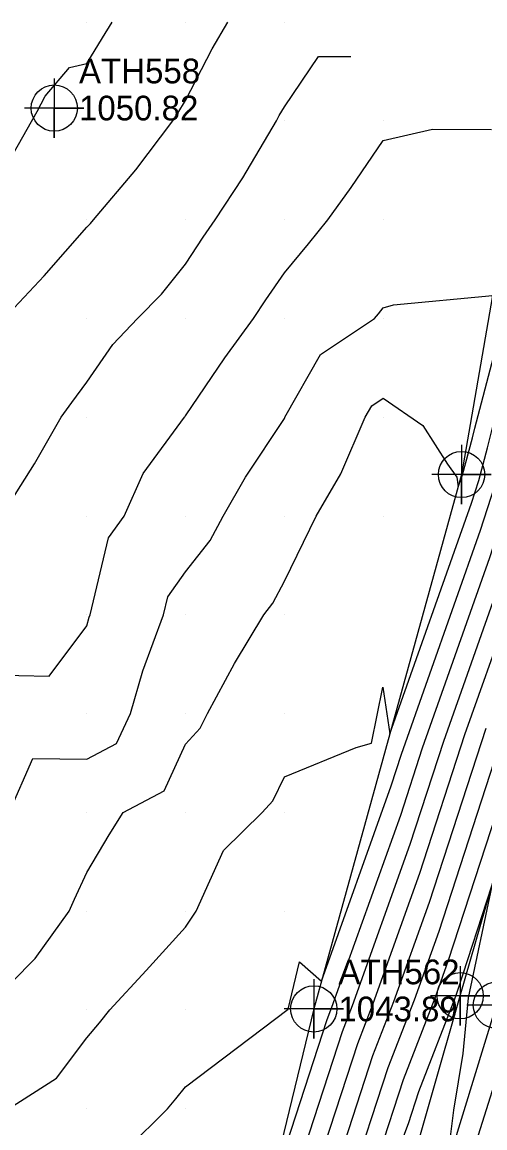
# Model space of a CAD drawing. Extents: x 1213164 to 1213550, y 766120 to 766870.
# Drawn here: x 1213343.5 to 1213390.3, y 766738.1 to 766850 of the extents above; entities that cross this region are included whole.
import ezdxf

# ---------------------------------------------------------------- set-up
doc = ezdxf.new("R2010")
doc.units = 0
for name, color, linetype in [('Default', 7, 'Continuous'), ('Exist DTM Breakline', 7, 'Continuous'), ('Exist DTM Breakline Cogo Elevation', 7, 'Continuous'), ('Exist DTM Breakline Cogo Number', 7, 'Continuous'), ('Exist DTM Breakline Cogo Point CELL', 7, 'Continuous'), ('Exist DTM QL2 LIDAR Elevation Point', 7, 'Continuous'), ('Exist DTM Regular Point CELL', 7, 'Continuous'), ('Exist DTM Regular Point Cogo Elevation', 7, 'Continuous'), ('Exist DTM Regular Point Cogo Number', 7, 'Continuous'), ('Exist Roads EOP', 7, 'Continuous')]:
    doc.layers.add(name, color=color, linetype=linetype)

msp = doc.modelspace()

# ---------------------------------------------------------------- linework, layer by layer
at = {"layer": 'Default'}
for points in [[(1213340, 766832.25), (1213344.98, 766840.96), (1213345.79, 766842.49), (1213348.26, 766845.39), (1213350, 766845.81), (1213351.59, 766848.41), (1213352.57, 766850)], [(1213341.65, 766820), (1213345.69, 766824.31), (1213350, 766829.23), (1213350.38, 766829.62), (1213350.69, 766830), (1213354.96, 766835.04), (1213358.72, 766840), (1213359.21, 766840.79), (1213360, 766842.08), (1213362.69, 766847.31), (1213364.29, 766850)], [(1213341.37, 766800), (1213344.71, 766805.29), (1213347.39, 766810), (1213348.5, 766811.5), (1213350, 766813.56), (1213352.62, 766817.38), (1213355.12, 766820), (1213357.55, 766822.45), (1213360, 766825.51), (1213361.77, 766828.23), (1213362.99, 766830), (1213365.78, 766834.22), (1213369.2, 766840), (1213369.47, 766840.53), (1213370, 766841.41), (1213373.47, 766846.53), (1213376.73, 766846.51)], [(1213340, 766783.91), (1213346.2, 766783.8), (1213350, 766788.89), (1213350.25, 766789.75), (1213350.34, 766790), (1213352.21, 766797.79), (1213353.79, 766800), (1213355.69, 766804.31), (1213359.89, 766810), (1213359.93, 766810.07), (1213360, 766810.13), (1213363.99, 766816.01), (1213366.89, 766820), (1213368.12, 766821.88), (1213370, 766824.61), (1213372.45, 766827.55), (1213374.39, 766830), (1213376.75, 766833.25), (1213380, 766838.01), (1213384.98, 766839.17), (1213390.96, 766839.14)], [(1213342.13, 766770), (1213344.53, 766775.47), (1213350, 766775.4), (1213353.02, 766776.98), (1213354.41, 766780), (1213355.68, 766784.32), (1213357.76, 766790), (1213358.19, 766791.81), (1213360, 766794.35), (1213362.49, 766797.51), (1213363.79, 766800), (1213366.06, 766803.94), (1213370, 766809.88), (1213370.04, 766809.96), (1213370.06, 766810), (1213373.65, 766816.35), (1213379.12, 766820), (1213379.52, 766820.48), (1213380, 766821.09), (1213381.06, 766821.37), (1213391.07, 766822.34), (1213394.9, 766836.82), (1213395.83, 766836.9), (1213397.41, 766836.69)], [(1213340, 766750.42), (1213344.78, 766755.22), (1213348.2, 766760), (1213348.77, 766761.23), (1213350, 766763.9), (1213352.27, 766767.73), (1213353.69, 766770), (1213357.83, 766772.17), (1213360, 766776.9), (1213361.49, 766778.51), (1213362.21, 766780), (1213364.94, 766785.06), (1213367.91, 766790), (1213368.83, 766791.17), (1213370, 766793.42), (1213373.21, 766800), (1213375.72, 766804.28), (1213378.18, 766810), (1213378.84, 766811.16), (1213380, 766811.94), (1213384.01, 766809.16), (1213386.52, 766805.24), (1213387.46, 766803.94), (1213387.6, 766802.97), (1213387.99, 766804.06), (1213388.02, 766804.17), (1213389.03, 766807.93), (1213389.27, 766808.9), (1213396.35, 766835.71)], [(1213342.06, 766740), (1213346.92, 766743.08), (1213350, 766747.18), (1213351.3, 766748.7), (1213352.34, 766750), (1213356.02, 766753.98), (1213360, 766758.38), (1213361.08, 766760), (1213363.85, 766766.15), (1213367.75, 766770), (1213368.83, 766771.17), (1213370, 766773.59), (1213377.27, 766776.57), (1213378.81, 766776.99), (1213379.96, 766782.67), (1213380.67, 766777.94), (1213388.93, 766801.31), (1213389.67, 766803.61), (1213390.55, 766806.91), (1213391.74, 766811.64), (1213397.81, 766834.6), (1213401.06, 766834.88), (1213406.54, 766834.16)], [(1213342.11, 766727.89), (1213344.49, 766730), (1213347.81, 766732.19), (1213350, 766733.54), (1213354.07, 766735.93), (1213358.17, 766740), (1213359.01, 766740.99), (1213360, 766742.21), (1213370.38, 766750.08), (1213371.54, 766754.87), (1213373.75, 766752.91), (1213380.81, 766772.67), (1213381.86, 766775.89), (1213389.86, 766798.56), (1213391.32, 766803.05), (1213392.08, 766805.9), (1213394.22, 766814.38), (1213399.26, 766833.49), (1213403.67, 766833.87), (1213411.11, 766832.9)], [(1213340, 766710.04), (1213345.86, 766714.14), (1213350, 766719.11), (1213350.56, 766720), (1213354.65, 766725.35), (1213360, 766728.23), (1213361.87, 766727.15), (1213367.98, 766729.52), (1213374.34, 766749.03), (1213374.82, 766750.27), (1213381.78, 766769.73), (1213384, 766776.55), (1213390.8, 766795.81), (1213392.96, 766802.49), (1213393.6, 766804.88), (1213396.69, 766817.13), (1213400.72, 766832.38), (1213406.29, 766832.86), (1213415.68, 766831.63)], [(1213342.11, 766697.89), (1213348.38, 766700), (1213349.6, 766700.4), (1213350, 766700.74), (1213351.46, 766701.5), (1213361.8, 766706.63), (1213364.87, 766714.3), (1213364.99, 766714.64), (1213366.77, 766720.25), (1213367.78, 766722.94), (1213375.88, 766747.81), (1213376.91, 766750.46), (1213382.75, 766766.79), (1213386.14, 766777.21), (1213391.74, 766793.06), (1213394.61, 766801.93), (1213395.13, 766803.87), (1213399.16, 766819.87), (1213402.17, 766831.27), (1213408.9, 766831.85), (1213420.25, 766830.36)], [(1213370.73, 766726.05), (1213377.43, 766746.6), (1213379, 766750.65), (1213383.72, 766763.85), (1213388.28, 766777.87), (1213392.68, 766790.31), (1213396.26, 766801.36), (1213396.65, 766802.85), (1213401.63, 766822.62), (1213403.63, 766830.16), (1213411.52, 766830.84), (1213416.18, 766830.23), (1213416.57, 766829.11), (1213419.9, 766816.1), (1213422.66, 766816.17), (1213430.02, 766816.29), (1213430.82, 766818.05), (1213431.59, 766819.95), (1213432.08, 766821.32), (1213432.69, 766823.44), (1213433.07, 766824.38), (1213433.31, 766826.18), (1213433.72, 766826.32)], [(1213379.6, 766735.4), (1213382.06, 766742.97), (1213385.26, 766751.21), (1213386.62, 766755.03), (1213394.71, 766779.84), (1213395.49, 766782.06), (1213401.2, 766799.68), (1213401.23, 766799.81), (1213402.66, 766805.49), (1213402.61, 766803.06), (1213402.28, 766799.28), (1213399.27, 766786.73), (1213397.9, 766779.79), (1213393.66, 766758.3), (1213393.59, 766756.35), (1213393.67, 766750.16), (1213393.67, 766750.1), (1213393.68, 766750.05), (1213394.97, 766742.85), (1213396.5, 766727.72)], [(1213376.64, 766732.28), (1213380.52, 766744.18), (1213383.17, 766751.03), (1213385.66, 766757.97), (1213392.57, 766779.18)], [(1213373.69, 766729.17), (1213378.97, 766745.39), (1213381.09, 766750.84), (1213384.69, 766760.91), (1213390.42, 766778.52)], [(1213373.54, 766714.54), (1213382.55, 766738.51), (1213383.61, 766741.75), (1213387.35, 766751.4), (1213387.59, 766752.09), (1213391.01, 766762.57), (1213388.61, 766751.23), (1213388.06, 766745.59), (1213387.11, 766739.86), (1213386.65, 766736.07)]]:
    msp.add_lwpolyline(points, dxfattribs=at)
at = {"layer": 'Exist DTM Breakline'}
for points in [[(1213393.73, 766837.71), (1213387.94, 766804.2), (1213372.97, 766750.1), (1213364.41, 766714.77), (1213354.91, 766685.16), (1213342.45, 766644.74), (1213315.98, 766668.51), (1213286.51, 766700.01), (1213270.13, 766717.65)], [(1213346.63, 766614.52), (1213356.15, 766642.33), (1213365.89, 766675.98), (1213376.51, 766712.04), (1213387.8, 766751.44), (1213401.65, 766799.53), (1213406.48, 766827.99)], [(1213348.97, 766613.21), (1213359.36, 766641.08), (1213368.17, 766674.74), (1213379.29, 766710.8), (1213391.46, 766750.47), (1213404.9, 766798.24), (1213409.09, 766827.1)]]:
    msp.add_lwpolyline(points, dxfattribs=at)
at = {"layer": 'Exist DTM Breakline Cogo Point CELL'}
for points in [[(1213387.94, 766807.2), (1213387.94, 766801.2), (1213387.94, 766804.2), (1213390.94, 766804.2), (1213384.94, 766804.2)], [(1213387.8, 766754.44), (1213387.8, 766748.44), (1213387.8, 766751.44), (1213390.8, 766751.44), (1213384.8, 766751.44)], [(1213372.97, 766753.1), (1213372.97, 766747.1), (1213372.97, 766750.1), (1213375.97, 766750.1), (1213369.97, 766750.1)], [(1213391.46, 766753.47), (1213391.46, 766747.47), (1213391.46, 766750.47), (1213394.46, 766750.47), (1213388.46, 766750.47)]]:
    msp.add_lwpolyline(points, dxfattribs=at)
for centre in [(1213387.94, 766804.2), (1213387.8, 766751.44), (1213372.97, 766750.1), (1213391.46, 766750.47)]:
    msp.add_circle(centre, 2.34, dxfattribs=at)
at = {"layer": 'Exist DTM QL2 LIDAR Elevation Point'}
for p, q in [((1213350, 766850), (1213350, 766850)), ((1213360, 766850), (1213360, 766850)), ((1213370, 766850), (1213370, 766850)), ((1213350, 766840), (1213350, 766840)), ((1213360, 766840), (1213360, 766840)), ((1213370, 766840), (1213370, 766840)), ((1213380, 766840), (1213380, 766840)), ((1213350, 766830), (1213350, 766830)), ((1213360, 766830), (1213360, 766830)), ((1213370, 766830), (1213370, 766830)), ((1213380, 766830), (1213380, 766830)), ((1213350, 766820), (1213350, 766820)), ((1213360, 766820), (1213360, 766820)), ((1213370, 766820), (1213370, 766820)), ((1213380, 766820), (1213380, 766820)), ((1213350, 766810), (1213350, 766810)), ((1213360, 766810), (1213360, 766810)), ((1213370, 766810), (1213370, 766810)), ((1213380, 766810), (1213380, 766810)), ((1213350, 766800), (1213350, 766800)), ((1213360, 766800), (1213360, 766800)), ((1213370, 766800), (1213370, 766800)), ((1213380, 766800), (1213380, 766800)), ((1213350, 766790), (1213350, 766790)), ((1213360, 766790), (1213360, 766790)), ((1213370, 766790), (1213370, 766790)), ((1213350, 766780), (1213350, 766780)), ((1213360, 766780), (1213360, 766780)), ((1213370, 766780), (1213370, 766780)), ((1213350, 766770), (1213350, 766770)), ((1213360, 766770), (1213360, 766770)), ((1213370, 766770), (1213370, 766770)), ((1213350, 766760), (1213350, 766760)), ((1213360, 766760), (1213360, 766760)), ((1213370, 766760), (1213370, 766760)), ((1213350, 766750), (1213350, 766750)), ((1213360, 766750), (1213360, 766750)), ((1213350, 766740), (1213350, 766740)), ((1213360, 766740), (1213360, 766740))]:
    msp.add_line(p, q, dxfattribs=at)
at = {"layer": 'Exist DTM Regular Point CELL'}
msp.add_lwpolyline([(1213346.71, 766844.3), (1213346.71, 766838.3), (1213346.71, 766841.3), (1213349.71, 766841.3), (1213343.71, 766841.3)], dxfattribs=at)
msp.add_circle((1213346.71, 766841.3), 2.34, dxfattribs=at)
at = {"layer": 'Exist Roads EOP'}
msp.add_line((1213381.4, 766711.12), (1213393.64, 766750.06), dxfattribs=at)
msp.add_spline([(1213390.23, 766668.75), (1213399.52, 766704.89), (1213412.3, 766744.74), (1213425.35, 766793.62), (1213431.78, 766824.82)], degree=3, dxfattribs=at)

# ---------------------------------------------------------------- texts
at = {"layer": 'Exist DTM Breakline Cogo Elevation'}
msp.add_text('1043.89', height=2.5, dxfattribs=at).set_placement((1213375.47, 766748.85))
at = {"layer": 'Exist DTM Breakline Cogo Number'}
msp.add_text('ATH562', height=2.5, dxfattribs=at).set_placement((1213375.47, 766752.6))
at = {"layer": 'Exist DTM Regular Point Cogo Elevation'}
msp.add_text('1050.82', height=2.5, dxfattribs=at).set_placement((1213349.21, 766840.05))
at = {"layer": 'Exist DTM Regular Point Cogo Number'}
msp.add_text('ATH558', height=2.5, dxfattribs=at).set_placement((1213349.21, 766843.8))

doc.saveas('drawing.dxf')
